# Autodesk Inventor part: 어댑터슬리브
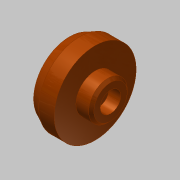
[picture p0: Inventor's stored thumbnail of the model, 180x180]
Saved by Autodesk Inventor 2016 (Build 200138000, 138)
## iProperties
Created: 2016-06
Part Number: 어댑터슬리브
Material: 강철, 탄소
Document SubType Name: Modeling
Designer: mduedu
Density: 7.87 g/cm^3
Appearance: 매끄러움 - 연한 주황색
Author: mduedu
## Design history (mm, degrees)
sketch "스케치2"
  geometry: L1 (0, 0)-(0, 14); L2 (0, 14)-(-4, 16); L3 (-4, 16)-(-10, 16); L4 (-10, 16)-(-10, 7.5); L5 (-10, 7.5)-(-16, 7.5); L6 (-16, 7.5)-(-16, 0); L7 (-16, 0)-(0, 0)
  constraints: 14 end point, 4 parallel, 1 perpendicular, 1 vertical
  dimensions: "d0" = 32 diameter of L3 L7; "d2" = 28 diameter of L1.end L7; "d3" = 6 distance of L2.end L3.end; "d4" = 6 distance of L4.end L5.end; "d5" = 15 diameter of L5 L7; "d6" = 16 distance between parallel lines of L6 L1
revolve "회전1" sketch "스케치2" stored, may be unused: angle "d7" = 90 deg
sketch "스케치3"
  geometry: L1 (-16, -7.5)-(-16, 7.5) reference; L2 (-16, 7.5)-(-10, 7.5) reference; L3 (-10, 7.5)-(-10, 16) reference; L4 (-10, 16)-(-4, 16) reference; L5 (-4, 16)-(0, 14) reference; L6 (0, 14)-(0, -14) reference; L7 (0, -14)-(-4, -16) reference; L8 (-4, -16)-(-10, -16) reference; L9 (-10, -16)-(-10, -7.5) reference; L10 (-10, -7.5)-(-16, -7.5) reference; L11 (0, 10)-(-5, 10); L12 (-5, 10)-(-5, 8); L13 (-5, 8)-(-7, 6); L14 (-7, 6)-(-7, 0); L15 (-7, 0)-(0, 0); L16 (0, 10)-(0, 0)
  constraints: 12 end point, 3 parallel, 2 perpendicular, 1 point on line
  dimensions: "d8" = 20 diameter of L11 L15; "d10" = 16 diameter of L12.end L15; "d11" = 12 diameter of L13.end L15; "d12" = 9 distance between parallel lines of L14 L1; "d13" = 2 distance between parallel lines of L12 L14
revolve "회전2" sketch "스케치3" stored, may be unused: angle "d14" = 90 deg
chamfer "모따기1" distance "d15" = 1; stored, may be unused: second distance "d16" = 2, angle "d17" = 45 deg
sketch "스케치4"
  geometry: 2 further points
  constraints: 1 coincident
sketch "스케치5"
  geometry: 1 further point
hole "구멍1" sketch "스케치5" at (0, 0) diameter "d18" = 4.5; stored, may be unused: countersink angle "d22" = 90 deg, drill point angle "d24" = 0 deg; dims "d19" = 6, "d20" = 8, "d21" = 4.6, "d23" = 8
node "솔리드1"
node "절단 모서리 투영1"
